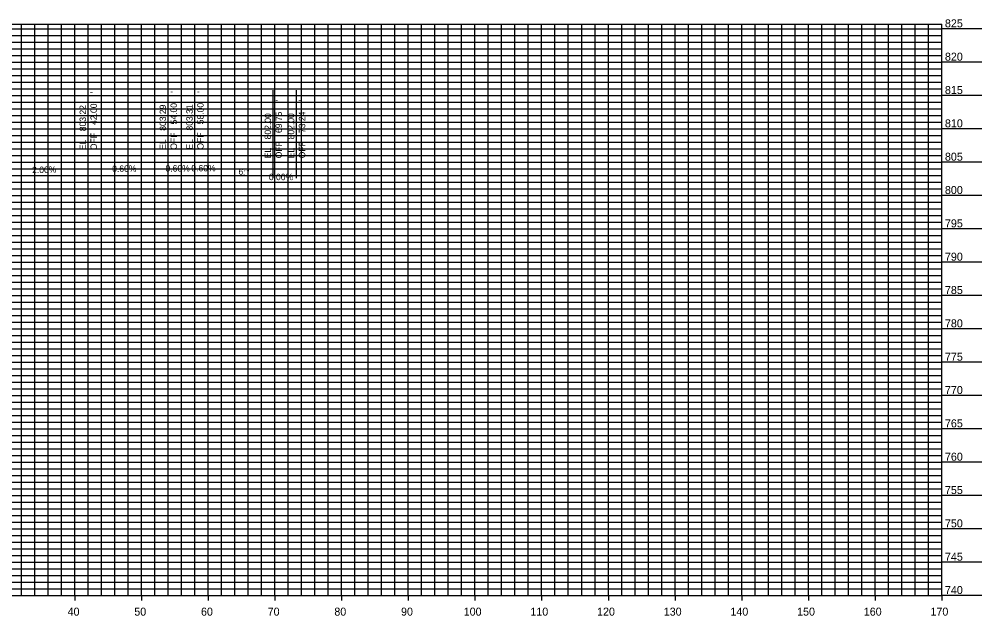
# Model space of a CAD drawing. Extents: x -116 to 176, y 733 to 826.
# Drawn here: x 31.7 to 176, y 737 to 826.5 of the extents above; entities that cross this region are included whole.
import ezdxf

# ---------------------------------------------------------------- set-up
doc = ezdxf.new("R2010")
doc.units = 0
for name, color, linetype in [('Default', 7, 'Continuous'), ('XS-Feature Text', 7, 'Continuous'), ('XS-Grid Lines', 7, 'Continuous'), ('XS-Segment Text', 7, 'Continuous'), ('XS-Sheet Major Grid Lines', 7, 'Continuous'), ('XS-Sheet Minor Grid Lines', 7, 'Continuous'), ('XS-Text', 7, 'Continuous')]:
    doc.layers.add(name, color=color, linetype=linetype)

msp = doc.modelspace()

# ---------------------------------------------------------------- linework, layer by layer
at = {"layer": 'XS-Feature Text'}
for p, q in [((42, 803.82), (42, 817.02)), ((54, 803.89), (54, 817.09)), ((58, 803.91), (58, 817.11)), ((69.75, 802.6), (69.75, 815.8)), ((73.24, 802.6), (73.24, 815.8))]:
    msp.add_line(p, q, dxfattribs=at)
at = {"layer": 'XS-Grid Lines'}
for p, q in [((-110, 825.71), (170, 825.71)), ((170, 740), (170, 825.71)), ((176, 825), (170, 825)), ((176, 820), (170, 820)), ((176, 815), (170, 815)), ((176, 810), (170, 810)), ((176, 805), (170, 805)), ((176, 800), (170, 800)), ((176, 795), (170, 795)), ((176, 790), (170, 790)), ((176, 785), (170, 785)), ((176, 780), (170, 780)), ((176, 775), (170, 775)), ((176, 770), (170, 770)), ((176, 765), (170, 765)), ((176, 760), (170, 760)), ((176, 755), (170, 755)), ((176, 750), (170, 750)), ((176, 745), (170, 745)), ((-110, 740), (170, 740)), ((40, 740), (40, 739.28)), ((50, 740), (50, 739.28)), ((60, 740), (60, 739.28)), ((70, 740), (70, 739.28)), ((80, 740), (80, 739.28)), ((90, 740), (90, 739.28)), ((100, 740), (100, 739.28)), ((110, 740), (110, 739.28)), ((120, 740), (120, 739.28)), ((130, 740), (130, 739.28)), ((140, 740), (140, 739.28)), ((150, 740), (150, 739.28)), ((160, 740), (160, 739.28)), ((170, 740), (170, 739.28)), ((176, 740), (170, 740))]:
    msp.add_line(p, q, dxfattribs=at)
at = {"layer": 'XS-Sheet Major Grid Lines'}
for p, q in [((40, 740), (40, 825.71)), ((50, 740), (50, 825.71)), ((60, 740), (60, 825.71)), ((70, 740), (70, 825.71)), ((80, 740), (80, 825.71)), ((90, 740), (90, 825.71)), ((100, 740), (100, 825.71)), ((110, 740), (110, 825.71)), ((120, 740), (120, 825.71)), ((130, 740), (130, 825.71)), ((140, 740), (140, 825.71)), ((150, 740), (150, 825.71)), ((160, 740), (160, 825.71)), ((-110, 825), (170, 825)), ((-110, 820), (170, 820)), ((-110, 815), (170, 815)), ((-110, 810), (170, 810)), ((-110, 805), (170, 805)), ((-110, 800), (170, 800)), ((-110, 795), (170, 795)), ((-110, 790), (170, 790)), ((-110, 785), (170, 785)), ((-110, 780), (170, 780)), ((-110, 775), (170, 775)), ((-110, 770), (170, 770)), ((-110, 765), (170, 765)), ((-110, 760), (170, 760)), ((-110, 755), (170, 755)), ((-110, 750), (170, 750)), ((-110, 745), (170, 745))]:
    msp.add_line(p, q, dxfattribs=at)
at = {"layer": 'XS-Sheet Minor Grid Lines'}
for p, q in [((32, 740), (32, 825.71)), ((34, 740), (34, 825.71)), ((36, 740), (36, 825.71)), ((38, 740), (38, 825.71)), ((42, 740), (42, 825.71)), ((44, 740), (44, 825.71)), ((46, 740), (46, 825.71)), ((48, 740), (48, 825.71)), ((52, 740), (52, 825.71)), ((54, 740), (54, 825.71)), ((56, 740), (56, 825.71)), ((58, 740), (58, 825.71)), ((62, 740), (62, 825.71)), ((64, 740), (64, 825.71)), ((66, 740), (66, 825.71)), ((68, 740), (68, 825.71)), ((72, 740), (72, 825.71)), ((74, 740), (74, 825.71)), ((76, 740), (76, 825.71)), ((78, 740), (78, 825.71)), ((82, 740), (82, 825.71)), ((84, 740), (84, 825.71)), ((86, 740), (86, 825.71)), ((88, 740), (88, 825.71)), ((92, 740), (92, 825.71)), ((94, 740), (94, 825.71)), ((96, 740), (96, 825.71)), ((98, 740), (98, 825.71)), ((102, 740), (102, 825.71)), ((104, 740), (104, 825.71)), ((106, 740), (106, 825.71)), ((108, 740), (108, 825.71)), ((112, 740), (112, 825.71)), ((114, 740), (114, 825.71)), ((116, 740), (116, 825.71)), ((118, 740), (118, 825.71)), ((122, 740), (122, 825.71)), ((124, 740), (124, 825.71)), ((126, 740), (126, 825.71)), ((128, 740), (128, 825.71)), ((132, 740), (132, 825.71)), ((134, 740), (134, 825.71)), ((136, 740), (136, 825.71)), ((138, 740), (138, 825.71)), ((142, 740), (142, 825.71)), ((144, 740), (144, 825.71)), ((146, 740), (146, 825.71)), ((148, 740), (148, 825.71)), ((152, 740), (152, 825.71)), ((154, 740), (154, 825.71)), ((156, 740), (156, 825.71)), ((158, 740), (158, 825.71)), ((162, 740), (162, 825.71)), ((164, 740), (164, 825.71)), ((166, 740), (166, 825.71)), ((168, 740), (168, 825.71)), ((-110, 824), (170, 824)), ((-110, 823), (170, 823)), ((-110, 822), (170, 822)), ((-110, 821), (170, 821)), ((-110, 819), (170, 819)), ((-110, 818), (170, 818)), ((-110, 817), (170, 817)), ((-110, 816), (170, 816)), ((-110, 814), (170, 814)), ((-110, 813), (170, 813)), ((-110, 812), (170, 812)), ((-110, 811), (170, 811)), ((-110, 809), (170, 809)), ((-110, 808), (170, 808)), ((-110, 807), (170, 807)), ((-110, 806), (170, 806)), ((-110, 804), (170, 804)), ((-110, 803), (170, 803)), ((-110, 802), (170, 802)), ((-110, 801), (170, 801)), ((-110, 799), (170, 799)), ((-110, 798), (170, 798)), ((-110, 797), (170, 797)), ((-110, 796), (170, 796)), ((-110, 794), (170, 794)), ((-110, 793), (170, 793)), ((-110, 792), (170, 792)), ((-110, 791), (170, 791)), ((-110, 789), (170, 789)), ((-110, 788), (170, 788)), ((-110, 787), (170, 787)), ((-110, 786), (170, 786)), ((-110, 784), (170, 784)), ((-110, 783), (170, 783)), ((-110, 782), (170, 782)), ((-110, 781), (170, 781)), ((-110, 779), (170, 779)), ((-110, 778), (170, 778)), ((-110, 777), (170, 777)), ((-110, 776), (170, 776)), ((-110, 774), (170, 774)), ((-110, 773), (170, 773)), ((-110, 772), (170, 772)), ((-110, 771), (170, 771)), ((-110, 769), (170, 769)), ((-110, 768), (170, 768)), ((-110, 767), (170, 767)), ((-110, 766), (170, 766)), ((-110, 764), (170, 764)), ((-110, 763), (170, 763)), ((-110, 762), (170, 762)), ((-110, 761), (170, 761)), ((-110, 759), (170, 759)), ((-110, 758), (170, 758)), ((-110, 757), (170, 757)), ((-110, 756), (170, 756)), ((-110, 754), (170, 754)), ((-110, 753), (170, 753)), ((-110, 752), (170, 752)), ((-110, 751), (170, 751)), ((-110, 749), (170, 749)), ((-110, 748), (170, 748)), ((-110, 747), (170, 747)), ((-110, 746), (170, 746)), ((-110, 744), (170, 744)), ((-110, 743), (170, 743)), ((-110, 742), (170, 742)), ((-110, 741), (170, 741))]:
    msp.add_line(p, q, dxfattribs=at)

# ---------------------------------------------------------------- texts
at = {"layer": 'Default'}
for s, p in [('825', (170.48, 825.24)), ('820', (170.48, 820.24)), ('815', (170.48, 815.24)), ('810', (170.48, 810.24)), ('805', (170.48, 805.24)), ('800', (170.48, 800.24)), ('795', (170.48, 795.24)), ('790', (170.48, 790.24)), ('785', (170.48, 785.24)), ('780', (170.48, 780.24)), ('775', (170.48, 775.24)), ('770', (170.48, 770.24)), ('765', (170.48, 765.24)), ('760', (170.48, 760.24)), ('755', (170.48, 755.24)), ('750', (170.48, 750.24)), ('745', (170.48, 745.24)), ('740', (170.48, 740.24))]:
    msp.add_text(s, height=1.2, dxfattribs=at).set_placement(p)
at = {"layer": 'XS-Feature Text'}
for s, p in [("'", (55.3, 815.41)), ("'", (59.3, 815.44)), ("'", (43.3, 815.34)), ("'", (71.05, 814.13)), ("'", (74.54, 814.13)), ('803.22', (41.66, 809.66)), ('42.00', (43.3, 810.61)), ('803.29', (53.66, 809.73)), ('54.00', (55.3, 810.68)), ('803.31', (57.66, 809.76)), ('58.00', (59.3, 810.7)), ('802.00', (69.41, 808.44)), ('69.75', (71.05, 809.39)), ('802.00', (72.9, 808.44)), ('73.24', (74.54, 809.39)), ('EL ', (41.66, 806.82)), ('OFF ', (43.3, 806.82)), ('EL ', (53.66, 806.89)), ('OFF ', (55.3, 806.89)), ('EL ', (57.66, 806.91)), ('OFF ', (59.3, 806.91)), ('EL ', (69.41, 805.6)), ('OFF ', (71.05, 805.6)), ('EL ', (72.9, 805.6)), ('OFF ', (74.54, 805.6))]:
    msp.add_text(s, height=0.96, rotation=90, dxfattribs=at).set_placement(p)
at = {"layer": 'XS-Segment Text'}
for s, rotation, p in [('2.00%', 1.1458, (33.59, 803.37)), ('0.60%', 0.3429, (45.59, 803.56)), ('0.60%', 0.3429, (53.59, 803.6)), ('0.60%', 0.3429, (57.47, 803.63)), ('6:1', 350.5375, (64.48, 803.2))]:
    msp.add_text(s, height=0.96, rotation=rotation, dxfattribs=at).set_placement(p)
msp.add_text('0.00%', height=0.96, dxfattribs=at).set_placement((69.09, 802.32))
at = {"layer": 'XS-Text'}
for s, p in [('40', (38.91, 737)), ('50', (48.91, 737)), ('60', (58.91, 737)), ('70', (68.91, 737)), ('80', (78.91, 737)), ('90', (88.91, 737)), ('100', (98.31, 737)), ('110', (108.31, 737)), ('120', (118.31, 737)), ('130', (128.31, 737)), ('140', (138.31, 737)), ('150', (148.31, 737)), ('160', (158.31, 737)), ('170', (168.31, 737))]:
    msp.add_text(s, height=1.2, dxfattribs=at).set_placement(p)

doc.saveas('drawing.dxf')
